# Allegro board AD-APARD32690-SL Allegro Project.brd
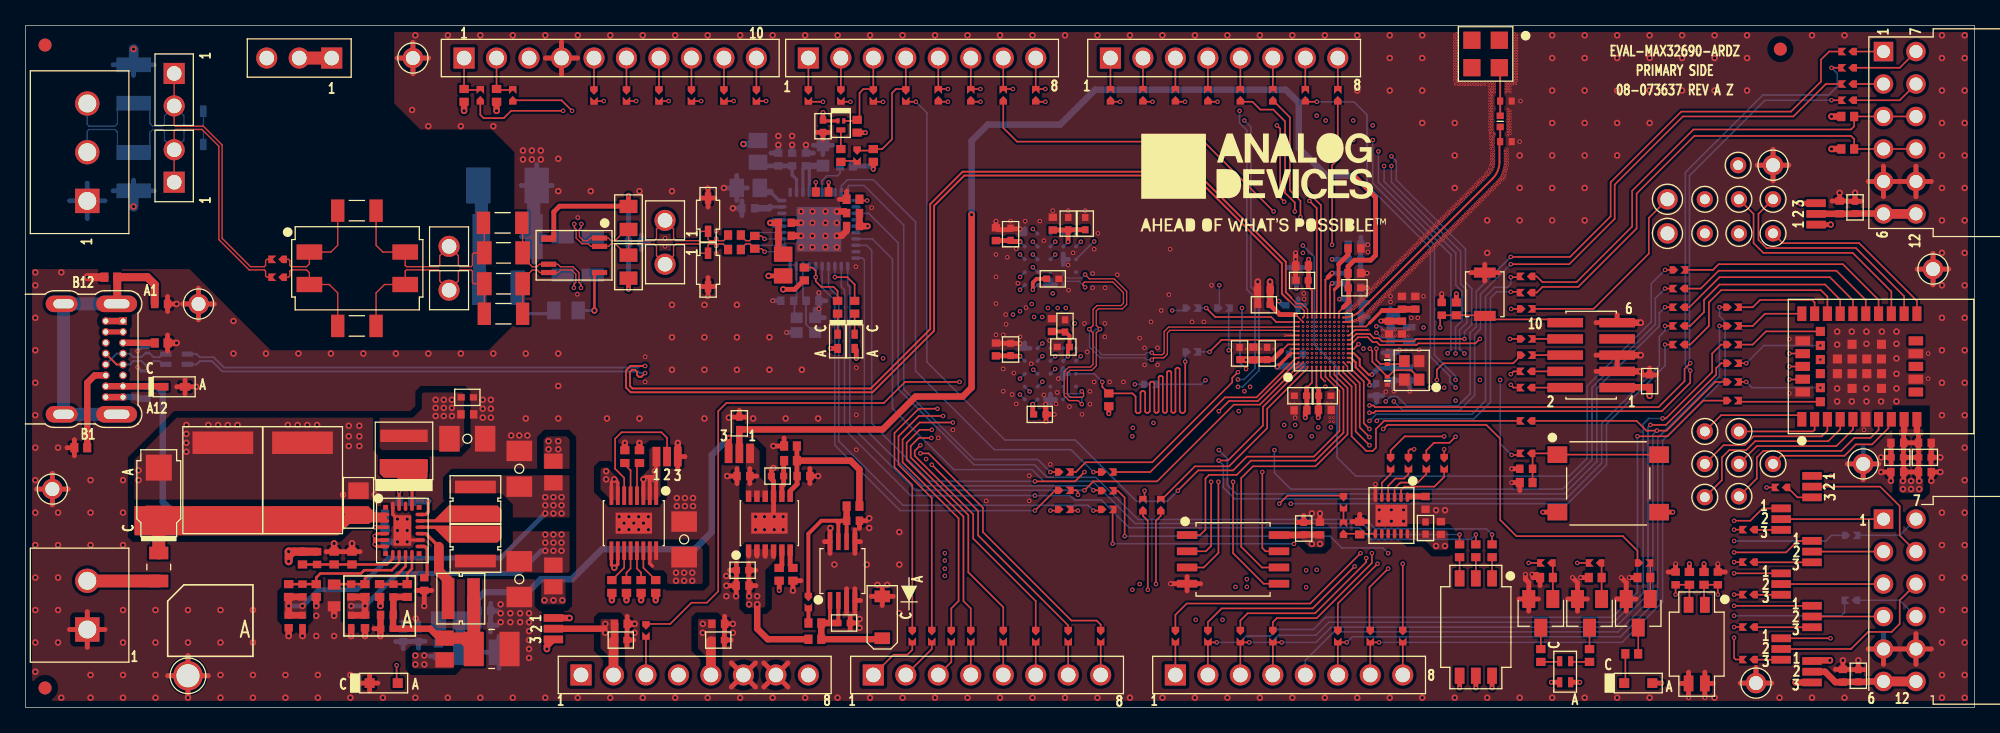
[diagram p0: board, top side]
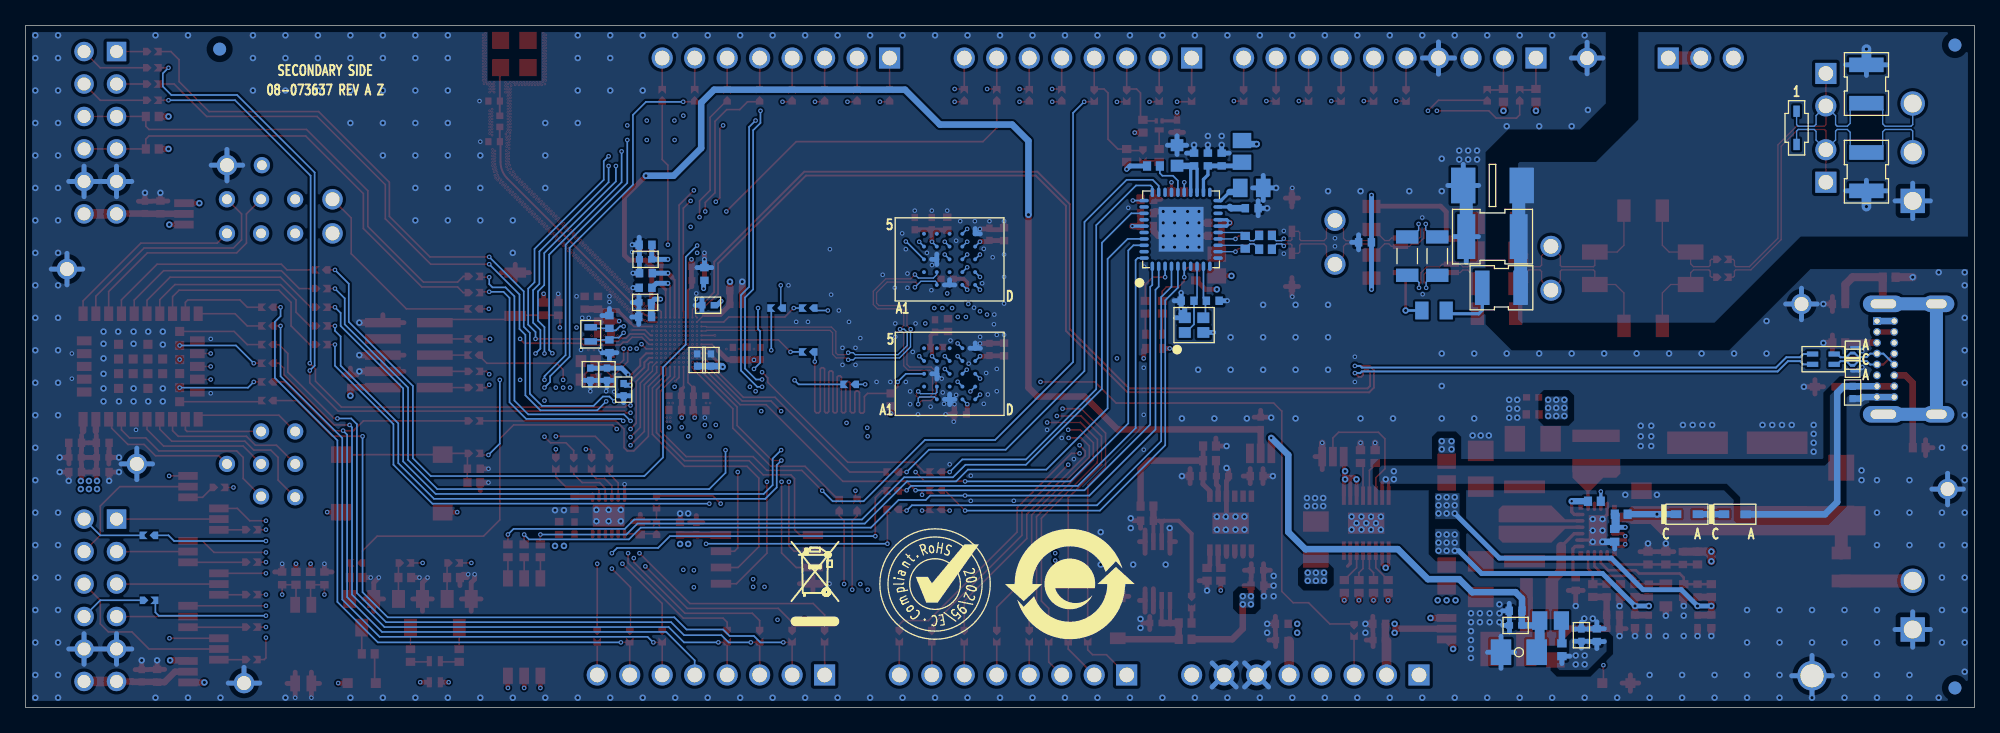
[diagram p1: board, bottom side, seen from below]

Outline 152.4 x 53.34 mm; copper layers: TOP, L2_GND, L3_SIG, L4_GND, L5_PWR, L6_PWR, L7_GND, L8_SIG, L9_GND, BOTTOM. Coordinates in mm from the lower left corner of the outline.
Outline path: 0,53.34 152.4,53.34 152.4,0 0,0 0,53.34

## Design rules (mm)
constraint set DEFAULT: min track width 0.127
net group 90_1: nets USB_DN_CM USB_DP_CM
net group 90_2: nets USB_DN USB_DP
net group 100_CLK: nets HYP_CLK_N HYP_CLK_P
net group 100C_1: nets PI+ PI-
net group 100C_2: nets UNNAMED_7_CHOKE4PV5_I912_N1 UNNAMED_7_CHOKE4PV5_I912_N2
net group 100C_3: nets UNNAMED_7_CAP_I819_N2 UNNAMED_7_CAP_I823_N2
net group 100C_4: nets UNNAMED_7_CAP_I819_N1 UNNAMED_7_CAP_I823_N1
net group 100C_5: nets TRX_N TRX_P
net group 100C_6: nets RXP TXN
net group 100C_7: nets RXN TXP

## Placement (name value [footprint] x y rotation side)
ANT1  479480001  [ASML126W126H161]  114.17 51.12 270 top
C1  4.7pF  [C0402]  22.8 11.68 90 top
C2  22uF  [CAPSML256W217H217]  21.65 17.78 270 top
C3  4.7uF  [C0805H53]  26.04 16 270 top
C4  4.7pF  [C0402]  21.65 9.14 270 top
C5  1uF  [C0402]  31.18 9.65 270 top
C6  4.7pF  [C0402]  25.46 9.14 270 top
C7  220uF  [C1210-2]  36.45 4.57 180 top
C8  47uF  [C1206H71]  34.54 21.02 180 top
C9  4.7pF  [C0402]  28.77 9.14 270 top
C10  47uF  [C1206H71]  38.61 10.03 90 top
C11  4.7uF  [C0402]  34.54 22.92 180 top
C12  47uF  [C1206H71]  38.61 18.67 270 top
C13  0.47uF  [C0402H22]  34.54 24.26 0 top
C14  47uF  [C1206H71]  51.5 13.14 270 top
C15  22uF  [CAPSML256W217H217]  15.43 17.78 270 top
C16  4.7uF  [C0402]  26.54 6.73 90 top
C17  4.7uF  [C0402]  28.26 7.24 0 top
C18  4700pF  [C0402]  103.92 35.91 0 top
C19  4.7uF  [C0402]  99.69 23.24 0 top
C20  0.47uF  [C0402H22]  99.69 24.38 180 top
C21  1uF  [C0402]  96.84 32.64 180 top
C22  1uF  [C0402]  103.89 33.97 0 bottom
C23  4.7uF  [C0402]  96.01 27.69 270 top
C24  1uF  [C0402]  103.95 30.54 0 bottom
C25  1uF  [C0402]  103.92 32.83 0 bottom
C26  1uF  [C0402]  103.92 36.2 0 bottom
C27  1uF  [C0402]  99.82 34.54 180 top
C28  1uF  [C0402]  101.6 23.27 0 top
C29  0.1uF  [C0402]  106.62 29.72 90 top
C30  0.1uF  [C0402]  107.63 31.65 270 top
C31  1uF  [C0402]  107.63 29.72 270 top
C32  0.47uF  [C0402H22]  94.93 27.69 90 top
C33  1uF  [C0402]  108.68 31.65 90 top
C34  4.7uF  [C0402]  29.53 5.65 270 bottom
C35  1uF  [C0402]  99.31 33.91 90 bottom
C36  0.47uF  [C0402H22]  30.73 5.65 90 bottom
C37  47uF  [C1206H71]  35.62 4.32 180 bottom
C38  4.7uF  [C0402]  35.88 7.56 180 bottom
C39  0.47uF  [C0402H22]  35.88 6.41 0 bottom
C40  1uF  [C0402]  101.22 14 90 top
C41  1.2pF  [C0402]  115.76 44.26 180 top
C42  0.47uF  [C0402H22]  62.36 45.47 270 top
C43  1.2pF  [C0402]  115.76 47.43 180 top
C44  12pF  [C0201]  106.49 25.55 270 top
C45  6PF  [C0402]  106.74 30.16 90 bottom
C46  1uF  [C0402]  80.33 37.85 90 top
C47  0.47uF  [C0402H22]  108.24 26.07 270 bottom
C48  4.7uF  [C0402]  103.92 33.97 180 top
C49  1uF  [C0402]  75.88 37.02 90 top
C50  0.47uF  [C0402H22]  99.03 31.46 0 bottom
C51  0.47uF  [C0402H22]  103.92 32.83 0 top
C52  12pF  [C0201]  106.49 27.18 90 top
C53  6PF  [C0402]  106.74 28.25 270 bottom
C54  1uF  [C0402]  75.88 28 90 top
C55  0.1uF  [C0402]  110.74 31.18 270 top
C56  0.47uF  [C0402H22]  101.6 24.38 0 top
C57  0.1uF  [C0402]  117.35 18.67 0 top
C58  0.47uF  [C0402H22]  97.09 27.69 90 top
C59  1uF  [C0402]  80.26 29.91 90 top
C60  0.47uF  [C0402H22]  103.95 31.69 0 bottom
C61  0.47uF  [C0402H22]  106.93 26.07 270 bottom
C62  15pF  [C0402]  61.53 31.81 0 bottom
C63  15pF  [C0402]  59.56 31.81 180 bottom
C64  0.01uF  [C0402]  59.37 37.91 180 top
C65  0.01uF  [C0402]  59.94 42.86 270 bottom
C66  0.47uF  [C0402H22]  98.81 27.18 90 bottom
C67  0.47uF  [C0402H22]  96.84 31.5 180 top
C68  0.68uF  [C0603]  62.36 43.18 90 bottom
C69  0.01uF  [C0402]  64.71 37.66 180 top
C70  0.47uF  [C0402H22]  99.82 33.4 180 top
C71  0.47uF  [C0402H22]  99.89 27.18 90 bottom
C72  0.1uF  [C0402]  56.52 39.05 0 bottom
C73  1UF  [C0805H55]  56.52 40.64 180 bottom
C74  0.47uF  [C0402H22]  105.63 24.86 270 bottom
C75  0.47uF  [C0402H22]  103.92 35.05 0 bottom
C76  0.47uF  [C0402H22]  99.95 14 90 top
C77  0.1uF  [C0402]  132.33 10.1 270 top
C78  0.1uF  [C0402]  129.03 10.1 270 top
C79  0.47uF  [C0402H22]  82.87 37.85 90 top
C80  0.47uF  [C0402H22]  81.53 37.85 90 top
C81  0.47uF  [C0402H22]  80.33 33.53 0 top
C82  0.47uF  [C0402H22]  77.03 37.02 90 top
C83  0.47uF  [C0402H22]  79.31 22.92 0 top
C84  0.47uF  [C0402H22]  77.03 28 90 top
C85  0.47uF  [C0402H22]  81.15 28.19 180 top
C86  0.01uF  [C0402]  146.37 20.7 180 top
C87  0.47uF  [C0402H22]  81.28 29.84 90 top
C88  0.1uF  [C0402]  58.86 42.86 90 bottom
C89  0.01uF  [C0402]  148.53 20.7 0 top
C90  0.1uF  [C0402]  59.37 36.89 0 top
C91  1uF  [C0402]  109.47 16 270 top
C92  0.1uF  [C0402]  64.71 38.67 0 top
C93  0.1uF  [C0402]  61.02 42.86 270 bottom
C94  0.1uF  [C0402]  47.66 36.39 0 bottom
C95  4.7uF  [C0402]  20.57 6.73 90 top
C96  0.47uF  [C0402H22]  21.65 6.73 270 top
C97  150pF  [C0805H30]  47.15 38.29 270 top
C98  0.47uF  [C0402H22]  25.46 6.73 270 top
C99  150pF  [C0805H30]  47.15 34.48 270 top
C100  0.47uF  [C0402H22]  28.26 6.16 180 top
C101  0.22uF  [C1206]  37.37 35.56 180 top
C102  0.22uF  [C1206]  37.37 33.15 180 top
C103  1000pF  [C1812H71]  37.69 36.83 180 bottom
C104  100PF  [C1210H75]  8.45 41.91 270 bottom
C105  100PF  [C1210H75]  36.99 32.83 180 bottom
C106  100PF  [C1210H75]  8.45 48.77 90 bottom
C107  4.7uF  [C0402]  46.55 6.54 180 top
C108  0.47uF  [C0402H22]  46.55 5.27 0 top
C109  4.7uF  [C0402]  141.86 39.12 270 top
C110  4.7uF  [C0402]  54.17 6.54 180 top
C111  0.47uF  [C0402H22]  143.07 39.12 90 top
C112  0.47uF  [C0402H22]  54.17 5.27 0 top
C113  4.7uF  [C0402]  142.11 2.48 270 top
C114  0.47uF  [C0402H22]  143.32 2.48 90 top
C115  4.7uF  [C0402]  146.37 18.41 0 top
C116  0.47uF  [C0402H22]  146.37 19.56 180 top
C117  4.7uF  [C0402]  148.53 18.41 180 top
C118  0.47uF  [C0402H22]  148.53 19.56 0 top
C119  0.47uF  [C0402H22]  127 25.53 90 top
C120  0.47uF  [C0402H22]  9.52 24.64 270 bottom
C121  4.7uF  [C0402]  110.68 14.03 270 top
C122  0.47uF  [C0402H22]  109.47 14.03 90 top
C123  0.1uF  [C0402]  10.6 31.56 180 top
C124  4.7uF  [C0402]  60.83 18.1 180 top
C125  2.2uF  [C0402H22]  58.8 18.1 0 top
C126  4.7uF  [C0402]  56.07 9.53 0 top
C127  0.47uF  [C0402H22]  56.07 10.73 180 top
C128  4.7uF  [C0402]  56.13 18.1 0 top
C129  0.47uF  [C0402H22]  55.82 22.23 90 top
C130  0.47uF  [C0402H22]  64.01 6.6 0 top
C131  4.7uF  [C0402]  64.71 14.61 180 top
D1  MBRA160T3G  [SMA]  10.41 16.76 90 top
D2  SP4020-01FTG  [SOD323_B]  53.37 38.54 90 top
D3  1N4148X-TP  [SOD523_B]  18.73 15.11 180 bottom
D4  1N4148X-TP  [SOD523_B]  22.48 15.11 180 bottom
D5  APTB1612ESGC-F01  [LEDSML63W49H33]  120.4 2.79 90 top
D6  SESD0201X1UN-0020-09  [D0201]  9.52 26.54 270 bottom
D7  SESD0201X1UN-0020-09  [D0201]  9.52 27.94 90 bottom
D8  D55V0M1B2WSQ-7  [SOD323_B]  13.91 45.34 270 bottom
D9  SP4020-01FTG  [SOD323_B]  53.37 34.23 270 top
D10  1N4148X-TP  [SOD523_B]  11.62 25.08 0 top
D11  BZT52C2V0-7-F  [SOD123-2]  66.99 7.05 90 top
DS1  LTST-S220TBKT  [LED0804]  28 1.91 0 top
DS2  LTST-S220TBKT  [LED0804]  126.11 1.91 0 top
DS3  APHHS1005CGCK  [LED0402_A]  64.83 28.64 270 top
DS4  APHHS1005LSYCK/J3-PF  [LED0402_A]  63.5 28.64 270 top
E1  100OHM  [L0805]  41.27 18.41 90 top
E2  100OHM  [L0805]  41.27 10.29 270 top
E3  100OHM  [L0805]  32.77 4.57 270 top
E4  100OHM  [L0805]  33.15 6.79 0 bottom
E5  100OHM  [L0805]  57.28 43.5 270 bottom
E6  100OHM  [L0805]  59.25 34.61 90 top
F3  0.5A  [F0805]  10.41 10.99 90 top
JP1  3PIN_SOLDER_JUMPER  [JPRSLD03]  50.16 19.62 0 top
JP2  3PIN_SOLDER_JUMPER  [JPRSLD03]  41.27 6.16 270 top
JP3  3PIN_SOLDER_JUMPER  [JPRSLD03]  140.02 38.61 90 top
JP4  3PIN_SOLDER_JUMPER  [JPRSLD03]  139.7 2.79 270 top
JP5  3PIN_SOLDER_JUMPER  [JPRSLD03]  139.7 17.27 270 top
JP6  3PIN_SOLDER_JUMPER  [JPRSLD03]  137.29 4.57 270 top
JP7  3PIN_SOLDER_JUMPER  [JPRSLD03]  139.7 12.19 270 top
JP8  3PIN_SOLDER_JUMPER  [JPRSLD03]  137.29 9.65 270 top
JP9  3PIN_SOLDER_JUMPER  [JPRSLD03]  137.29 14.73 270 top
JP10  3PIN_SOLDER_JUMPER  [JPRSLD03]  139.7 7.11 270 top
JP11  3PIN_SOLDER_JUMPER  [JPRSLD03]  55.82 19.88 180 top
L1  600nH  [LSMSQ118H47]  34.04 8.51 0 top
L2  1.2UH  [LSMSQ157H122]  29.59 20.07 90 top
L3  1.5uH  [LSMSQ118H47]  35.18 16.26 90 top
L4  1uH  [LSMSQ118H47]  35.18 12.45 270 top
L5  4.3nH  [L0402]  115.32 45.85 90 top
L6  470UH  [LSML236W362H209]  25.94 34.35 270 top
L7  90OHMS AT 100MEGHZ  [L0805-4PH39]  11.81 27.24 180 bottom
M1  NINA-W102  [MNINA_W102]  145.1 26.67 0 top
NOREF  -  []  0 0 0 top
NOREF#2  -  []  152.4 0 0 top
NOREF#3  -  []  341.38 170.56 0 top
NOREF#4  -  []  225.37 211.79 0 top
NOREF#5  -  []  0 0 0 top
NOREF#6  -  []  -258.95 193.29 0 top
NOREF#7  -  []  244.09 60.96 0 top
NOREF#8  -  []  96.81 41.05 0 top
NOREF#9  -  [unnamed#2]  137.22 51.5 0 top
NOREF#10  -  [unnamed#2]  1.52 1.52 0 top
NOREF#11  -  []  69.6 126.24 0 top
NOREF#12  -  []  152.4 0 90 top
NOREF#13  -  []  152.4 53.34 180 top
NOREF#14  -  []  344.17 60.96 0 top
NOREF#15  -  [unnamed#2]  1.52 51.82 0 top
NOREF#16  -  []  -66.58 -125.62 0 top
NOREF#17  -  []  4.83 6.1 0 top
NOREF#18  -  []  43.43 2.54 0 top
NOREF#19  -  []  0 0 0 top
NOREF#20  -  []  0 53.34 270 top
NOREF#21  -  []  0 53.34 0 top
NOREF#22  -  []  -66.6 -125.65 0 top
NOREF#23  -  []  -66.68 -125.73 0 top
NOREF#24  -  []  152.4 0 90 top
NOREF#25  -  []  82.37 285.07 0 top
NOREF#26  -  []  0 53.34 0 top
NOREF#27  -  []  4.83 6.1 0 top
NOREF#28  -  []  252.22 67.07 0 top
NOREF#29  -  [unnamed#2]  137.22 51.5 180 bottom
NOREF#30  -  []  70.74 9.65 180 bottom
NOREF#31  -  [unnamed#2]  1.52 1.52 180 bottom
NOREF#32  -  [unnamed#2]  1.52 51.82 180 bottom
NOREF#33  -  []  90.87 6.41 180 bottom
NOREF#34  -  []  81.28 9.65 180 bottom
P1  TBP02R2-381-03BE  [CNCUITBP02R2-381-03]  4.83 39.62 90 top
P2  SSQ-108-03-G-S  [CNSAMTECSSQ-108-XX-X-S]  43.43 2.54 0 top
P3  SSQ-108-03-G-S  [CNSAMTECSSQ-108-XX-X-S]  66.29 2.54 0 top
P4  SSQ-108-03-G-S  [CNSAMTECSSQ-108-XX-X-S]  89.92 2.54 0 top
P5  SSQ-110-03-G-S  [CNSAMTECSSQ-110-XX-X-S]  34.29 50.8 0 top
P6  SSQ-108-03-G-S  [CNSAMTECSSQ-108-XX-X-S]  61.21 50.8 0 top
P7  SSQ-108-03-G-S  [CNSAMTECSSQ-108-XX-X-S]  84.84 50.8 0 top
P8  PPPC062LJBN-RC  [CNHDRRA2X6H205]  145.29 14.73 270 top
P9  FTSH-105-01-L-DV-K  [CNHDR2X5H245]  122.43 27.56 90 top
P10  2137160001  [CNMOLEX2137160001]  7.62 30.23 270 top
P11  TSW-103-07-G-S  [CNTHMHDR1X3L300W98H343]  23.94 50.8 180 top
P12  TSW-101-07-G-S  [CNTHMHDR1X1L100W100H343]  50.01 38.1 180 top
P13  PPPC062LJBN-RC  [CNHDRRA2X6H205]  145.29 51.31 270 top
P14  TBP02R2-381-02  [CNCUITTBP02R2-381-02]  4.83 6.1 90 top
P15  TSW-101-07-G-S  [CNTHMHDR1X1L100W100H343]  50.01 34.67 180 top
P16  TSW-102-07-G-S  [CNTHMHDR1X2L200W98H343]  11.62 49.59 270 top
P17  TSW-102-07-G-S  [CNTHMHDR1X2L200W98H343]  11.62 41.08 90 top
P18  NCSOLDER_BRIDGE  [NCSB]  65.02 43.18 270 top
P19  NCSOLDER_BRIDGE  [NCSB]  133.48 24 0 top
P20  NCSOLDER_BRIDGE  [NCSB]  133.48 25.46 0 top
P21  NCSOLDER_BRIDGE  [NCSB]  133.48 26.92 0 top
P22  NCSOLDER_BRIDGE  [NCSB]  133.48 28.38 0 top
P23  NCSOLDER_BRIDGE  [NCSB]  103.06 13.97 90 top
P24  1405-2  [CNKEY1405-2]  2.1 17.08 0 top
P25  1405-2  [CNKEY1405-2]  136.65 42.42 0 top
P26  0338-0-15-15-15-27-10-0  [CNMILLMAX0338]  12.7 2.48 0 top
P27  1405-2  [CNKEY1405-2]  149.16 34.29 0 top
P28  1405-2  [CNKEY1405-2]  13.53 31.56 0 top
P29  1405-2  [CNKEY1405-2]  143.7 19.05 0 top
P30  1405-2  [CNKEY1405-2]  135.32 1.91 0 top
P31  1405-2  [CNKEY1405-2]  30.29 50.8 0 top
P32  1999-3  [CNKEY1999-3]  131.32 21.59 0 top
P33  1999-3  [CNKEY1999-3]  133.98 21.59 0 top
P34  1999-3  [CNKEY1999-3]  131.32 19.05 0 top
P35  1999-3  [CNKEY1999-3]  131.32 16.45 0 top
P36  1999-3  [CNKEY1999-3]  133.98 19.05 0 top
P37  NCSOLDER_BRIDGE  [NCSB]  61.21 8.25 270 top
P38  1405-2  [CNKEY1405-2]  128.4 39.75 0 top
P39  1405-2  [CNKEY1405-2]  128.4 37.08 0 top
P40  1999-3  [CNKEY1999-3]  133.98 16.51 0 top
P41  1999-3  [CNKEY1999-3]  136.65 19.05 0 top
P42  1999-3  [CNKEY1999-3]  136.65 37.08 0 top
P43  1999-3  [CNKEY1999-3]  136.65 39.75 0 top
P44  1999-3  [CNKEY1999-3]  133.98 39.75 0 top
P45  NCSOLDER_BRIDGE  [NCSB]  133.48 31.31 0 top
P46  NCSOLDER_BRIDGE  [NCSB]  133.48 29.84 0 top
P47  1999-3  [CNKEY1999-3]  133.92 42.42 0 top
P48  1999-3  [CNKEY1999-3]  131.32 39.75 0 top
P49  1999-3  [CNKEY1999-3]  131.32 37.08 0 top
P52  1999-3  [CNKEY1999-3]  133.98 37.08 0 top
P53  TSW-101-07-G-S  [CNTHMHDR1X1L100W100H343]  33.12 36.07 0 top
P54  TSW-101-07-G-S  [CNTHMHDR1X1L100W100H343]  33.12 32.64 0 top
Q1  BSS138LT1G  [SOT23]  126.11 7.37 180 top
Q2  BSS138LT1G  [SOT23]  118.49 7.37 180 top
Q3  BSS138LT1G  [SOT23]  122.3 7.37 180 top
Q4  DMP32D5SFB-7B  [DFN3_1X0_6]  63.75 45.53 270 top
R1  1MEG  [R0402]  21.65 11.68 90 top
R2  191K  [R0402]  25.53 11.68 270 top
R3  5.76K  [R0402]  27.62 15.11 180 bottom
R4  1K  [R0402]  28.13 13.46 270 bottom
R5  1MEG  [R0402]  20.57 9.14 270 top
R6  316K  [R0402]  22.73 9.14 90 top
R7  1MEG  [R0402]  26.54 9.14 270 top
R8  806K  [R0603]  24.13 8.76 90 top
R9  124  [R0402]  48.01 19.62 270 top
R10  124  [R0402]  46.86 19.62 270 top
R11  374K  [R0402]  29.84 9.14 270 top
R12  1MEG  [R0402]  27.69 9.14 90 top
R13  47K  [R0402]  46.99 9.46 270 top
R14  47K  [R0402]  48.13 9.46 270 top
R15  47K  [R0402]  49.28 9.46 270 top
R16  47K  [R0402]  45.85 9.46 270 top
R17  1K  [R0402]  29.72 16.13 180 bottom
R18  NCSOLDER_BRIDGE  [NCSB]  87.95 25.27 0 bottom
R20  NCSOLDER_BRIDGE  [NCSB]  117.35 22.42 180 top
R21  NCSOLDER_BRIDGE  [NCSB]  68.83 47.88 270 top
R22  NCSOLDER_BRIDGE  [NCSB]  84.58 15.49 0 top
R24  NCSOLDER_BRIDGE  [NCSB]  84.58 18.41 0 top
R29  NCSOLDER_BRIDGE  [NCSB]  81.22 18.41 0 top
R30  NCSOLDER_BRIDGE  [NCSB]  122.75 11.3 180 top
R31  NCSOLDER_BRIDGE  [NCSB]  88.77 15.81 90 top
R32  NCSOLDER_BRIDGE  [NCSB]  117.35 33.72 180 top
R33  NCSOLDER_BRIDGE  [NCSB]  134.75 11.37 180 top
R34  NCSOLDER_BRIDGE  [NCSB]  134.75 6.29 180 top
R35  NCSOLDER_BRIDGE  [NCSB]  142.75 8.38 180 bottom
R36  NCSOLDER_BRIDGE  [NCSB]  129.29 32.77 180 top
R37  NCSOLDER_BRIDGE  [NCSB]  129.29 29.84 180 top
R38  NCSOLDER_BRIDGE  [NCSB]  93.66 31.24 0 bottom
R43  NCSOLDER_BRIDGE  [NCSB]  63.75 47.88 270 top
R44  NCSOLDER_BRIDGE  [NCSB]  44.45 47.88 270 top
R45  NCSOLDER_BRIDGE  [NCSB]  46.99 47.88 270 top
R46  NCSOLDER_BRIDGE  [NCSB]  54.61 47.88 270 top
R47  NCSOLDER_BRIDGE  [NCSB]  91.19 27.81 0 bottom
R48  NCSOLDER_BRIDGE  [NCSB]  66.29 47.88 270 top
R49  NCSOLDER_BRIDGE  [NCSB]  84.58 16.95 0 top
R53  NCSOLDER_BRIDGE  [NCSB]  118.94 11.3 180 top
R54  NCSOLDER_BRIDGE  [NCSB]  87.38 15.81 90 top
R55  NCSOLDER_BRIDGE  [NCSB]  81.22 16.99 0 top
R56  NCSOLDER_BRIDGE  [NCSB]  81.22 15.49 0 top
R57  NCSOLDER_BRIDGE  [NCSB]  117.35 32.45 180 top
R58  NCSOLDER_BRIDGE  [NCSB]  134.75 13.91 180 top
R59  NCSOLDER_BRIDGE  [NCSB]  134.75 8.83 180 top
R60  NCSOLDER_BRIDGE  [NCSB]  134.75 3.75 180 top
R61  NCSOLDER_BRIDGE  [NCSB]  137.29 17.21 180 top
R62  NCSOLDER_BRIDGE  [NCSB]  129.29 31.31 180 top
R63  NCSOLDER_BRIDGE  [NCSB]  129.29 28.38 180 top
R65  NCSOLDER_BRIDGE  [NCSB]  91.19 31.24 0 bottom
R69  NCSOLDER_BRIDGE  [NCSB]  52.07 47.88 270 top
R70  NCSOLDER_BRIDGE  [NCSB]  61.21 47.88 270 top
R71  NCSOLDER_BRIDGE  [NCSB]  117.35 19.88 180 top
R72  NCSOLDER_BRIDGE  [NCSB]  49.53 47.88 270 top
R73  NCSOLDER_BRIDGE  [NCSB]  57.15 47.88 270 top
R74  NCSOLDER_BRIDGE  [NCSB]  126.56 11.3 0 top
R75  NCSOLDER_BRIDGE  [NCSB]  108.14 19.11 270 top
R76  NCSOLDER_BRIDGE  [NCSB]  106.74 19.11 270 top
R77  NCSOLDER_BRIDGE  [NCSB]  84.84 47.88 90 top
R78  NCSOLDER_BRIDGE  [NCSB]  89.92 47.88 90 top
R79  NCSOLDER_BRIDGE  [NCSB]  117.35 28.83 0 top
R80  NCSOLDER_BRIDGE  [NCSB]  73.91 47.88 90 top
R81  NCSOLDER_BRIDGE  [NCSB]  71.37 47.88 90 top
R82  NCSOLDER_BRIDGE  [NCSB]  38.1 47.88 90 top
R83  NCSOLDER_BRIDGE  [NCSB]  48.51 6.03 270 top
R84  NCSOLDER_BRIDGE  [NCSB]  95 47.88 90 top
R85  NCSOLDER_BRIDGE  [NCSB]  100.08 47.88 90 top
R86  NCSOLDER_BRIDGE  [NCSB]  89.92 5.59 270 top
R87  NCSOLDER_BRIDGE  [NCSB]  97.54 5.59 270 top
R88  NCSOLDER_BRIDGE  [NCSB]  102.62 5.59 270 top
R89  NCSOLDER_BRIDGE  [NCSB]  69.34 5.59 270 top
R90  NCSOLDER_BRIDGE  [NCSB]  72.39 5.59 270 top
R91  NCSOLDER_BRIDGE  [NCSB]  76.45 5.59 270 top
R92  NCSOLDER_BRIDGE  [NCSB]  81.53 5.59 270 top
R93  NCSOLDER_BRIDGE  [NCSB]  103.06 16.07 270 top
R94  NCSOLDER_BRIDGE  [NCSB]  117.35 31.18 0 top
R95  NCSOLDER_BRIDGE  [NCSB]  110.93 19.11 270 top
R96  NCSOLDER_BRIDGE  [NCSB]  109.54 19.11 270 top
R97  NCSOLDER_BRIDGE  [NCSB]  107.7 5.59 270 top
R98  NCSOLDER_BRIDGE  [NCSB]  87.38 47.88 90 top
R99  NCSOLDER_BRIDGE  [NCSB]  92.46 47.88 90 top
R100  NCSOLDER_BRIDGE  [NCSB]  117.35 27.56 0 top
R101  NCSOLDER_BRIDGE  [NCSB]  76.45 47.88 90 top
R102  NCSOLDER_BRIDGE  [NCSB]  78.99 47.88 90 top
R103  NCSOLDER_BRIDGE  [NCSB]  35.56 47.88 90 top
R104  NCSOLDER_BRIDGE  [NCSB]  142.75 13.46 0 bottom
R105  NCSOLDER_BRIDGE  [NCSB]  97.54 47.88 90 top
R106  NCSOLDER_BRIDGE  [NCSB]  102.62 47.88 90 top
R107  NCSOLDER_BRIDGE  [NCSB]  95 5.59 270 top
R108  NCSOLDER_BRIDGE  [NCSB]  92.46 5.59 270 top
R109  NCSOLDER_BRIDGE  [NCSB]  105.16 5.59 270 top
R110  NCSOLDER_BRIDGE  [NCSB]  70.87 5.59 270 top
R111  NCSOLDER_BRIDGE  [NCSB]  73.91 5.59 270 top
R112  NCSOLDER_BRIDGE  [NCSB]  78.99 5.59 270 top
R113  NCSOLDER_BRIDGE  [NCSB]  84.07 5.59 270 top
R114  NCSOLDER_BRIDGE  [NCSB]  129.29 34.23 0 top
R115  10K  [R0402]  126.56 10.16 180 top
R116  499  [R0402]  125.6 4.19 180 top
R117  10K  [R0402]  118.94 10.16 180 top
R118  499  [R0402]  118.49 4.06 270 top
R119  10K  [R0402]  117.35 17.59 180 top
R120  10K  [R0402]  111.89 31.18 270 top
R121  10K  [R0402]  122.75 10.16 180 top
R122  499  [R0402]  122.3 4.06 270 top
R123  TBD0402  [R0402]  24.13 11.68 90 top
R124  1  [R0402]  32.26 4.51 90 bottom
R125  1.5K  [R0402]  64.2 42.35 0 bottom
R126  2.7K  [R0402]  66.29 43.18 270 top
R127  10  [R0402]  63.75 43.18 270 top
R128  10K  [R0402]  60.9 33.91 90 top
R129  10K  [R0402]  57.02 36.39 270 top
R130  4.7K  [R0402]  63.5 31.31 90 top
R131  49.9  [R0402]  55.44 36.93 180 bottom
R132  100K  [R0402]  65.02 45.47 90 top
R133  10K  [R0402]  131.25 10.1 270 top
R134  49.9  [R0402]  55.44 35.81 180 top
R135  10K  [R0402]  57.02 36.39 90 bottom
R136  10K  [R0402]  130.11 10.1 270 top
R137  10K  [R0402]  64.71 39.75 0 top
R138  4.7K  [R0402]  114.68 12.26 270 top
R139  4.7K  [R0402]  64.83 31.31 90 top
R140  4.99K  [R0402]  55.44 36.96 180 top
R141  10K  [R0402]  142.49 43.69 0 top
R142  10K  [R0402]  142.49 46.23 0 top
R143  10K  [R0402]  36.83 47.88 270 top
R144  10K  [R0402]  34.29 47.88 270 top
R145  1K  [R0402]  6.67 33.66 180 top
R146  4.99K  [R0402]  55.44 35.85 180 bottom
R147  4.7MEG  [R2010]  37.69 40.83 180 bottom
R148  0  [R1206]  44.35 35.31 270 bottom
R149  1MEG  [R1206]  37.31 37.91 180 top
R150  1MEG  [R1206]  37.37 30.8 180 top
R151  0  [R1206]  42.01 35.31 270 bottom
R152  100  [R0805]  42.26 31.05 180 bottom
R153  10K  [R1206]  25.91 38.86 180 top
R154  10K  [R1206]  25.91 29.84 180 top
R155  NCSOLDER_BRIDGE  [NCSB]  19.72 35.05 180 top
R156  NCSOLDER_BRIDGE  [NCSB]  19.72 33.66 180 top
R157  5.1K  [R0402]  10.6 28.51 180 top
R158  5.1K  [R0402]  4.32 20.32 0 top
R159  NCSOLDER_BRIDGE  [NCSB]  117.35 26.29 180 top
R160  NCSOLDER_BRIDGE  [NCSB]  142.49 51.31 180 top
R161  NCSOLDER_BRIDGE  [NCSB]  142.49 50.04 180 top
R162  NCSOLDER_BRIDGE  [NCSB]  117.35 25.02 180 top
R163  NCSOLDER_BRIDGE  [NCSB]  142.49 48.77 180 top
R164  NCSOLDER_BRIDGE  [NCSB]  142.49 47.5 180 top
R165  10K  [R0402]  104.33 14.03 90 top
R166  4.7K  [R0402]  112.14 12.26 270 top
R167  4.7K  [R0402]  113.41 12.26 270 top
R168  1.5K  [R0402]  62.29 40.32 0 top
R169  4.99K  [R0402]  59.82 19.3 180 top
R170  200K  [R0402]  58.93 10.41 90 top
R171  499  [R0402]  60.01 10.41 90 top
R172  47K  [R0402]  61.72 6.6 180 top
R173  499  [R0402]  61.72 5.33 180 top
R174  1K  [R0402]  64.71 15.75 0 top
R175  200K  [R0402]  59.82 20.45 0 top
R176  10K  [R0402]  84.71 24.07 270 top
S1  B3U-1000P  [SWSML118W98H69]  114.11 32.32 90 top
S2  PTS645SH50SMTR92LFS  [SWSMSQ236H197]  123.76 17.53 270 top
S3  KAN1102RT  [SWSML148W177H69]  130.68 4.95 180 top
S4  416131160803  [SWSML196W228H98]  113.41 6.29 180 top
T1  74930000  [TSML185W127H114_A]  42.89 35.37 180 top
U1  MAX32690GWE+  [WLCSP140_4_492X4_532H0_69]  101.47 28.57 90 top
U2  ADIN1110CCPZ  [QFN40_6X6_PAD3_5X3_5]  62.04 37.4 180 bottom
U3  LT8692SIV#PBF  [QFN20_4X3_PAD2_40X1_40_05-08-1524]  29.46 13.84 270 top
U4  LTC4415EMSE#PBF  [MSOP16_PAD2_845X1_651]  47.56 14.41 180 top
U5  MX25U6432FM2I02  [SOP8_A]  94.42 11.58 270 top
U6  S80KS5122GABHM020  [BGA24_8X6]  80.14 35.05 180 bottom
U7  S80KS5122GABHM020  [BGA24_8X6]  80.14 26.1 180 bottom
U8  MAXQ1065GTC+  [DFN12_3X3_PAD2_5X1_7]  106.81 15.01 180 top
U9  LT3040EMSE#PBF  [MSOP12_PAD2_845X1_651]  58.17 14.41 0 top
U10  LTC6655BHMS8-1.25#PBF  [MSOP8]  63.88 10.67 0 top
Y1  25MEGHZ  [YSML79W63H20]  61.02 29.91 180 bottom
Y2  32MEGHZ  [YSML79W63H20]  108.39 26.37 90 top
Y3  32.768KHZ  [YSML65W41H20]  108.2 29.19 270 bottom

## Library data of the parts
ANT1 = ANT4P_V3: User Part Number: UPN; Tolerance: N/A; alternate symbols: (); part number: ANT4P_V3_SM-479480001,E061377,ASML126W126H161; tolerance: N/A
C1 C4 C6 C9 = CAP: User Part Number: UPN; Tolerance: 0.05pF; alternate symbols: (C0402L); part number: CAP_SM-4.7PF,50V,0.05PF,E021938,C0402; tolerance: 0.05pF
C2 C15 = CAP: Tolerance: 20; User Part Number: UPN; alternate symbols: (); part number: CAP_SM-22UF,50V,20,E017662,CAPSML256W217H217; tolerance: 20
C3 = CAP: Tolerance: 10; User Part Number: UPN; alternate symbols: (); part number: CAP_SM-4.7UF,50V,10,E028468,C0805H53; tolerance: 10
C5 C21 C22 C24-C28 C31 C33 C35 C40 C46 C49 C54 C59 C91 = CAP: User Part Number: UPN; Tolerance: 10; alternate symbols: (C0402L); part number: CAP_SM-1UF,16V,10,E019219,C0402; tolerance: 10
C7 = CAP: Tolerance: 20; User Part Number: UPN; alternate symbols: (); part number: CAP_SM-220UF,6.3V,20,E031200,C1210-2; tolerance: 20
C8 C10 C12 C14 C37 = CAP: Tolerance: 20; User Part Number: UPN; alternate symbols: (); part number: CAP_SM-47UF,16V,20,E033215,C1206H71; tolerance: 20
C11 C16 C17 C19 C23 C34 C38 C48 C95 C107 C109 C110 C113 C115 C117 C121 C124 C126 C128 C131 = CAP: User Part Number: UPN; Tolerance: 10; alternate symbols: (C0402L); part number: CAP_SM-4.7UF,6.3V,10,E020089,C0402; tolerance: 10
C13 C20 C32 C36 C39 C42 C47 C50 C51 C56 C58 C60 C61 C66 C67 C70 C71 C74-C76 C79-C85 C87 C96 C98 C100 C108 C111 C112 C114 C116 C118-C120 C122 C127 C129 C130 = CAP: Tolerance: 10; User Part Number: UPN; alternate symbols: C0402L_ALT; part number: CAP_SM-0.47UF,6.3V,10,E030257,C0402H22; tolerance: 10
C18 = CAP: User Part Number: UPN; Tolerance: 10; alternate symbols: (C0402L); part number: CAP_SM-4700PF,50V,10,E000289,C0402; tolerance: 10
C29 C30 C55 C57 C72 C77 C78 C88 C90 C92-C94 C123 = CAP: User Part Number: UPN; Tolerance: 10; alternate symbols: (C0402L_ALT,C0402L); part number: CAP_SM-0.1UF,50V,10,E026461,C0402; tolerance: 10
C41 C43 = CAP: User Part Number: UPN; Tolerance: 0.25pF; alternate symbols: (C0402L); part number: CAP_SM-1.2PF,50V,0.25PF,E032690,C0402; tolerance: 0.25pF
C44 C52 = CAP: Tolerance: 5; User Part Number: UPN; alternate symbols: (C0201L); part number: CAP_SM-12PF,50V,5,E020029,C0201; tolerance: 5
C45 C53 = CAP: User Part Number: UPN; Tolerance: 0.1pF; alternate symbols: (C0402L); part number: CAP_SM-6PF,50V,0.1PF,E045002,C0402; tolerance: 0.1pF
C62 C63 = CAP: User Part Number: UPN; Tolerance: 1; alternate symbols: (C0402L); part number: CAP_SM-15PF,50V,1,E020722,C0402; tolerance: 1
C64 C65 C69 = CAP: User Part Number: UPN; Tolerance: 10; alternate symbols: (C0402L); part number: CAP_SM-0.01UF,100V,10,E032295,C0402; tolerance: 10
C68 = CAP: User Part Number: UPN; Tolerance: 10; alternate symbols: (C0603L); part number: CAP_SM-0.68UF,10V,10,E035107,C0603; tolerance: 10
C73 = CAP: User Part Number: UPN; Tolerance: 10; alternate symbols: (); part number: CAP_SM-1UF,100V,10,E048499,C0805H55; tolerance: 10
C86 C89 = CAP: User Part Number: UPN; Tolerance: 10; alternate symbols: (C0402L); part number: CAP_SM-0.01UF,25V,10,E013688,C0402; tolerance: 10
C97 C99 = CAP: Tolerance: 1; User Part Number: UPN; alternate symbols: (); part number: CAP_SM-150PF,50V,1,E033595,C0805H30; tolerance: 1
C101 C102 = CAP: User Part Number: UPN; Tolerance: 10; alternate symbols: (C1206L); part number: CAP_SM-0.22UF,50V,10,E013767,C1206; tolerance: 10
C103 = CAP: Tolerance: 10; User Part Number: UPN; alternate symbols: (); part number: CAP_SM-1000PF,3000V,10,E023441,C1812H71; tolerance: 10
C104-C106 = CAP: User Part Number: UPN; Tolerance: 10; alternate symbols: (); part number: CAP_SM-100PF,2000V,10,E048915,C1210H75; tolerance: 10
C125 = CAP: Tolerance: 20; User Part Number: UPN; alternate symbols: (); part number: CAP_SM-2.2UF,6.3V,20,E015930,C0402H22; tolerance: 20
D1 = DIOSCHOTTKY: User Part Number: UPN; Tolerance: N/A; alternate symbols: (); part number: DIOSCHOTTKY_SM-MBRA160T3G,60V,N/A,E005910,SMA; tolerance: N/A
D2 D9 = DIOZNR_V4: Tolerance: N/A; User Part Number: UPN; alternate symbols: (); part number: DIOZNR_V4_SM-SP4020-01FTG,3.3V,N/A,E028177,SOD323_B; tolerance: N/A
D3 D4 D10 = DIO: Tolerance: N/A; User Part Number: UPN; alternate symbols: (); part number: DIO_SM-1N4148X-TP,75V,N/A,E039538,SOD523_B; tolerance: N/A
D5 = DIOLED_4P_V5: Tolerance: www.kingbright.com; User Part Number: UPN; alternate symbols: (); part number: DIOLED_4P_V5_SM-APTB1612ESGC-F01,2V/2.2V,N/A,E028120,LEDSML63W49H33; tolerance: www.kingbright.com
D6 D7 = DIO: Tolerance: N/A; User Part Number: UPN; alternate symbols: (); part number: DIO_SM-SESD0201X1UN-0020-09,9V,N/A,E022225,D0201; tolerance: N/A
D8 = DIOZNR_V2: Tolerance: N/A; User Part Number: UPN; alternate symbols: (); part number: DIOZNR_V2_SM-D55V0M1B2WSQ-7,100V,N/A,E048935,SOD323_B; tolerance: N/A
D11 = DIOZNR: User Part Number: UPN; Tolerance: 5; alternate symbols: (); part number: DIOZNR_SM-BZT52C2V0-7-F,2V,5,E026228,SOD123-2; tolerance: 5
DS1 DS2 = DIOLED: User Part Number: UPN; Tolerance: N/A; alternate symbols: LED0804_RA; part number: DIOLED_SM-LTST-S220TBKT,3.3V,N/A,E026167,LED0804; tolerance: N/A
DS3 = DIOLED: User Part Number: UPN; Tolerance: N/A; alternate symbols: (); part number: DIOLED_SM-APHHS1005CGCK,2.1V,N/A,E029804,LED0402_A; tolerance: N/A
DS4 = DIOLED: User Part Number: UPN; Tolerance: N/A; alternate symbols: (); part number: DIOLED_SM-APHHS1005LSYCK/J3-PF,1.85V,N/A,E032958,LED0402_A; tolerance: N/A
E1-E6 = FERRITE: User Part Number: UPN; Tolerance: 25; alternate symbols: (L0805L); part number: FERRITE_SM-100OHM,25,E012241,L0805; tolerance: 25
F3 = FSFUSE: User Part Number: UPN; Tolerance: N/A; alternate symbols: (); part number: FSFUSE_SM-0.5A,6V,E016128,F0805; tolerance: N/A
JP1-JP11 = NC3P_JMPR: Tolerance: N/A; User Part Number: UPN; alternate symbols: (); part number: NC3P_JMPR_SM-3PIN_SOLDER_JUMPER,E005606,JPRSLD03; tolerance: N/A
L1 = IND: Tolerance: 20; User Part Number: UPN; alternate symbols: (); part number: IND_SM-600NH,20,E019410,LSMSQ118H47; tolerance: 20
L2 = IND: User Part Number: UPN; Tolerance: 20; alternate symbols: (); part number: IND_SM-1.2UH,20,E030942,LSMSQ157H122; tolerance: 20
L3 = IND: Tolerance: 20; User Part Number: UPN; alternate symbols: (); part number: IND_SM-1.5UH,20,E022829,LSMSQ118H47; tolerance: 20
L4 = IND: Tolerance: 20; User Part Number: UPN; alternate symbols: (); part number: IND_SM-1UH,20,E015810,LSMSQ118H47; tolerance: 20
L5 = IND: User Part Number: UPN; Tolerance: 0.3nH; alternate symbols: (L0402L); part number: IND_SM-4.3NH,0.3NH,E017364,L0402; tolerance: 0.3nH
L6 = CHOKE4P_V5: User Part Number: UPN; Tolerance: 50; alternate symbols: (); part number: CHOKE4P_V5_SM-470UH,50,E032119,LSML236W362H209; tolerance: 50
L7 = CHOKE4P: User Part Number: UPN; Tolerance: 25; alternate symbols: (); part number: CHOKE4P_SM-90OHMS AT 100MEGHZ,25,E027226,L0805-4PH39; tolerance: 25
M1 = MODNINA_W10X: User Part Number: UPN; Tolerance: N/A; alternate symbols: (); part number: MODNINA_W10X_SM-NINA-W102,E038406,MNINA_W102; tolerance: N/A
P1 = CN3P: User Part Number: UPN; Tolerance: N/A; alternate symbols: (); part number: CN3P_TH-TBP02R2-381-03BE,E061218,CNCUITBP02R2-381-03; tolerance: N/A
P2-P4 P6 P7 = CN8P_A: User Part Number: UPN; Tolerance: N/A; alternate symbols: (); part number: CN8P_A_TH-SSQ-108-03-G-S,E020478,CNSAMTECSSQ-108-XX-X-S; tolerance: N/A
P5 = CN10P: User Part Number: UPN; Tolerance: N/A; alternate symbols: (); part number: CN10P_TH-SSQ-110-03-G-S,E020479,CNSAMTECSSQ-110-XX-X-S; tolerance: N/A
P8 P13 = CN12P_V3: User Part Number: UPN; Tolerance: N/A; alternate symbols: (); part number: CN12P_V3_TH-PPPC062LJBN-RC,E022332,CNHDRRA2X6H205; tolerance: N/A
P9 = CN10P_ODD_EVEN: Tolerance: N/A; User Part Number: UPN; alternate symbols: (); part number: CN10P_ODD_EVEN_SM-FTSH-105-01-L-DV-K,E023407,CNHDR2X5H245; tolerance: N/A
P10 = CN16PAB_4GND: Tolerance: N/A; User Part Number: UPN; alternate symbols: (); part number: CN16PAB_4GND_TH-2137160001,E052752,CNMOLEX2137160001; tolerance: N/A
P11 = CN3P: User Part Number: UPN; Tolerance: N/A; alternate symbols: (); part number: CN3P_TH-TSW-103-07-G-S,E042653,CNTHMHDR1X3L300W98H343; tolerance: N/A
P12 P15 P53 P54 = CN1P: User Part Number: UPN; Tolerance: N/A; alternate symbols: (); part number: CN1P_TH-TSW-101-07-G-S,E028213,CNTHMHDR1X1L100W100H343; tolerance: N/A
P14 = CN2P: Tolerance: N/A; alternate symbols: (); part number: CN2P_TH-TBP02R2-381-02BE,E061381,CNCUITTBP02R2-381-02; tolerance: N/A
P16 P17 = CN2P: User Part Number: UPN; Tolerance: N/A; alternate symbols: (); part number: CN2P_TH-TSW-102-07-G-S,E031850,CNTHMHDR1X2L200W98H343; tolerance: N/A
P18-P23 P37 P45 P46 = NC2P: User Part Number: UPN; Tolerance: N/A; alternate symbols: (); part number: NC2P_SM-NCSOLDER_BRIDGE,E043778,NCSB; tolerance: N/A
P24 P25 P27-P31 P38 P39 = CN1P: Tolerance: N/A; User Part Number: UPN; alternate symbols: (); part number: CN1P_TH-1405-2,E022242,CNKEY1405-2; tolerance: N/A
P26 = CN1P: User Part Number: UPN; Tolerance: N/A; alternate symbols: (); part number: CN1P_TH-0338-0-15-15-15-27-10-0,E057326,CNMILLMAX0338; tolerance: N/A
P32-P36 P40-P44 P47-P49 P52 = CN1P: Tolerance: N/A; User Part Number: UPN; alternate symbols: (); part number: CN1P_TH-1999-3,E020606,CNKEY1999-3; tolerance: N/A
Q1-Q3 = TRANNMOSFET_V8: User Part Number: UPN; Tolerance: N/A; part number: TRANNMOSFET_V8_SM-BSS138LT1G,E018770,SOT23; tolerance: N/A
Q4 = TRANPMOSFET_V17: User Part Number: UPN; Tolerance: N/A; alternate symbols: (); part number: TRANPMOSFET_V17_SM-DMP32D5SFB-7B,E031823,DFN3_1X0_6; tolerance: N/A
R1 R5 R7 R12 = RES: User Part Number: UPN; Tolerance: 1; alternate symbols: (R0402L); part number: RES_SM-1MEG,E003749,1/10W,1,R0402; tolerance: 1
R2 = RES: User Part Number: UPN; Tolerance: 1; alternate symbols: (R0402L); part number: RES_SM-191K,E035329,1/10W,1,R0402; tolerance: 1
R3 = RES: User Part Number: UPN; Tolerance: 1; alternate symbols: (R0402L); part number: RES_SM-5.76K,E025055,1/10W,1,R0402; tolerance: 1
R4 R17 R145 R174 = RES: User Part Number: UPN; Tolerance: 1; alternate symbols: (R0402L,R0402L_ALT); part number: RES_SM-1K,E003763,1/10W,1,R0402; tolerance: 1
R6 = RES: User Part Number: UPN; Tolerance: 1; alternate symbols: (R0402L); part number: RES_SM-316K,E008277,1/10W,1,R0402; tolerance: 1
R8 = RES: User Part Number: UPN; Tolerance: 1; alternate symbols: (R0603L); part number: RES_SM-806K,E033372,1/10W,1,R0603; tolerance: 1
R9 R10 = RES: User Part Number: UPN; Tolerance: 1; alternate symbols: (R0402L); part number: RES_SM-124,E043017,1/10W,1,R0402; tolerance: 1
R11 = RES: User Part Number: UPN; Tolerance: 1; alternate symbols: (R0402L); part number: RES_SM-374K,E022652,1/10W,1,R0402; tolerance: 1
R13-R16 R172 = RES: User Part Number: UPN; Tolerance: 1; alternate symbols: (R0402L,R0402L_ALT); part number: RES_SM-47K,E008189,1/10W,1,R0402; tolerance: 1
R18 R20-R22 R24 R29-R38 R43-R49 R53-R63 R65 R69-R114 R155 R156 R159-R164 = NC2P: User Part Number: UPN; Tolerance: N/A; alternate symbols: (R0402L,R0402L_ALT); part number: NC2P_SM-NCSOLDER_BRIDGE,E043778,NCSB; tolerance: N/A
R115 R117 R119-R121 R128 R129 R133 R135-R137 R141-R144 R165 R176 = RES: User Part Number: UPN; Tolerance: 1; alternate symbols: (R0402L,R0402L_ALT); part number: RES_SM-10K,E003751,1/10W,1,R0402; tolerance: 1
R116 R118 R122 R171 R173 = RES: User Part Number: UPN; Tolerance: 1; alternate symbols: (R0402L); part number: RES_SM-499,E003758,1/10W,1,R0402; tolerance: 1
R123 = RES: User Part Number: UPN; alternate symbols: (R0402L,R0402L_ALT); part number: RES_SM-TBD0402,E004049,TBD0402,TBD0402,R0402
R124 = RES: User Part Number: UPN; alternate symbols: (R0402L); part number: RES_SM-1,E020530,1/6W,1,R0402
R125 R168 = RES: User Part Number: UPN; Tolerance: 1; alternate symbols: (R0402L); part number: RES_SM-1.5K,E003782,1/10W,1,R0402; tolerance: 1
R126 = RES: User Part Number: UPN; Tolerance: 1; alternate symbols: (R0402L); part number: RES_SM-2.7K,E007440,1/10W,1,R0402; tolerance: 1
R127 = RES: User Part Number: UPN; Tolerance: 5; alternate symbols: (R0402L); part number: RES_SM-10,E042731,1/10W,5,R0402; tolerance: 5
R130 R138 R139 R166 R167 = RES: User Part Number: UPN; Tolerance: 5; alternate symbols: (R0402L); part number: RES_SM-4.7K,E042730,1/10W,5,R0402; tolerance: 5
R131 R134 = RES: User Part Number: UPN; Tolerance: 1; alternate symbols: (R0402L); part number: RES_SM-49.9,E003750,1/10W,1,R0402; tolerance: 1
R132 = RES: User Part Number: UPN; Tolerance: 5; alternate symbols: (R0402L); part number: RES_SM-100K,E003464,1/10W,5,R0402; tolerance: 5
R140 R146 R169 = RES: User Part Number: UPN; Tolerance: 1; alternate symbols: (R0402L); part number: RES_SM-4.99K,E006643,1/10W,1,R0402; tolerance: 1
R147 = RES: Tolerance: 5; User Part Number: UPN; alternate symbols: (R2010L); part number: RES_SM-4.7MEG,E031023,1/2W,5,R2010; tolerance: 5
R148 R151 = RES: User Part Number: UPN; Tolerance: 5; alternate symbols: (R1206L); part number: RES_SM-0,E010093,1/4W,5,R1206; tolerance: 5
R149 R150 = RES: User Part Number: UPN; Tolerance: 1; alternate symbols: (R1206L); part number: RES_SM-1MEG,E003331,1/4W,1,R1206; tolerance: 1
R152 = RES: User Part Number: UPN; Tolerance: 1; alternate symbols: (R0805L); part number: RES_SM-100,E003481,1/8W,1,R0805; tolerance: 1
R153 R154 = RES: User Part Number: UPN; Tolerance: 1; alternate symbols: (R1206L); part number: RES_SM-10K,E003285,1/4W,1,R1206; tolerance: 1
R157 R158 = RES: User Part Number: UPN; Tolerance: 0.1; alternate symbols: (R0402L); part number: RES_SM-5.1K,E010267,1/16W,0.1,R0402; tolerance: 0.1
R170 R175 = RES: User Part Number: UPN; Tolerance: 1; alternate symbols: (R0402L); part number: RES_SM-200K,E004033,1/10W,1,R0402; tolerance: 1
S1 = SWSPST2PIN_V2: Tolerance: N/A; User Part Number: UPN; alternate symbols: (); part number: SWSPST2PIN_V2_SM-B3U-1000P,E016303,SWSML118W98H69; tolerance: N/A
S2 = SWSPST4PIN_B: User Part Number: UPN; Tolerance: N/A; alternate symbols: (); part number: SWSPST4PIN_B_SM-PTS645SH50SMTR92LFS,E019204,SWSMSQ236H197; tolerance: N/A
S3 = SWSPST4P_V8: User Part Number: UPN; Tolerance: N/A; alternate symbols: (); part number: SWSPST4P_V8_SM-KAN1102RT,E059268,SWSML148W177H69; tolerance: N/A
S4 = SWSPST6PIN: Tolerance: N/A; User Part Number: UPN; alternate symbols: (); part number: SWSPST6PIN_SM-416131160803,E034219,SWSML196W228H98; tolerance: N/A
T1 = XFMR7P_V2: User Part Number: UPN; Tolerance: N/A; alternate symbols: (TSML185W127H114_B); part number: XFMR7P_V2_SM-74930000,E042298,TSML185W127H114_A; tolerance: N/A
U1 = ADMAX32690: User Part Number: UPN; Tolerance: N/A; alternate symbols: (WLCSP140_4_492X4_532H0_69_L); part number: ADMAX32690_SM-MAX32690GWE+,E058743,WLCSP140_4_492X4_532H0_69; tolerance: N/A
U2 = ADIN1110_V2: User Part Number: UPN; Tolerance: N/A; alternate symbols: (); part number: ADIN1110_V2_SM-ADIN1110CCPZ,E049968,QFN40_6X6_PAD3_5X3_5; tolerance: N/A
U3 = ADLT8692S: User Part Number: UPN; Tolerance: N/A; alternate symbols: (); part number: ADLT8692S_SM-LT8692SIV#PBF,E058915,QFN20_4X3_PAD2_40X1_40_05-08-1524; tolerance: N/A
U4 = LINLTC4415: Tolerance: N/A; User Part Number: UPN; alternate symbols: (); part number: LINLTC4415_SM-LTC4415EMSE#PBF,E027536,MSOP16_PAD2_845X1_651; tolerance: N/A
U5 = ICMX25U6432F_V2: User Part Number: UPN; Tolerance: N/A; alternate symbols: (); part number: ICMX25U6432F_V2_SM-MX25U6432FM2I02,E060310,SOP8_A; tolerance: N/A
U6 U7 = ICS80KS5122: Tolerance: N/A; User Part Number: UPN; alternate symbols: (BGA24_8X6_PB); part number: ICS80KS5122_SM-S80KS5122GABHM020,E060311,BGA24_8X6; tolerance: N/A
U8 = ADMAXQ1065: User Part Number: UPN; Tolerance: N/A; alternate symbols: (); part number: ADMAXQ1065_SM-MAXQ1065GTC+,E059230,DFN12_3X3_PAD2_5X1_7; tolerance: N/A
U9 = ADLT3040: Tolerance: N/A; User Part Number: UPN; alternate symbols: (); part number: ADLT3040_SM-LT3040EMSE#PBF,E040922,MSOP12_PAD2_845X1_651; tolerance: N/A
U10 = LINLTC6655: Tolerance: N/A; User Part Number: UPN; alternate symbols: (); part number: LINLTC6655_SM-LTC6655BHMS8-1.25#PBF,E032393,MSOP8; tolerance: N/A
Y1 = XTAL4PIN_V3: Tolerance: 10PPM; User Part Number: UPN; alternate symbols: (); part number: XTAL4PIN_V3_SM-25MEGHZ,E051324,YSML79W63H20; tolerance: 10PPM
Y2 = XTAL4PIN_V3: Tolerance: N/A; User Part Number: UPN; alternate symbols: (); part number: XTAL4PIN_V3_SM-32MEGHZ,E017803,YSML79W63H20; tolerance: N/A
Y3 = XTAL: User Part Number: UPN; Tolerance: 20PPM; alternate symbols: (); part number: XTAL_SM-32.768KHZ,E058949,YSML65W41H20; tolerance: 20PPM

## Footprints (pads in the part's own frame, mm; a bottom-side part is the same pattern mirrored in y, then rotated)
ASML126W126H161
  rect 1.346x1.346 smd: 1(-1.073,1.073) 2(-1.073,-1.073) 3(1.073,-1.073) 4(1.073,1.073)
BGA24_8X6
  round 0.305 smd: A2(-2,-1) A3(-2,0) A4(-2,1) A5(-2,2) B1(-1,-2) B2(-1,-1) B3(-1,0) B4(-1,1) B5(-1,2) C1(0,-2) C2(0,-1) C3(0,0) C4(0,1) C5(0,2) D1(1,-2) D2(1,-1) D3(1,0) D4(1,1) D5(1,2) E1(2,-2) E2(2,-1) E3(2,0) E4(2,1) E5(2,2)
C0201
  rect 0.305x0.406 smd: 1(-0.318,0) 2(0.318,0)
C0402
  rect 0.584x0.66 smd: 1(-0.5,0) 2(0.5,0)
C0402H22
  rect 0.559x0.508 smd: 1(-0.479,0) 2(0.479,0)
C0603
  rect 0.94x0.991 smd: 1(-0.8,0) 2(0.8,0)
C0805H30
  rect 1.041x1.397 smd: 1(-0.9,0) 2(0.9,0)
C0805H53
  rect 1.295x1.6 smd: 1(-0.953,0) 2(0.953,0)
C0805H55
  rect 1.143x1.448 smd: 1(-0.9,0) 2(0.9,0)
C1206
  rect 1.143x1.803 smd: 1(-1.5,0) 2(1.5,0)
C1206H71
  rect 1.6x2.007 smd: 1(-1.397,0) 2(1.397,0)
C1210-2
  rect 1.575x2.692 smd: 1(-1.397,0) 2(1.397,0)
C1210H75
  rect 1.143x2.692 smd: 1(-1.5,0) 2(1.5,0)
C1812H71
  rect 1.397x3.505 smd: 1(-2.05,0) 2(2.05,0)
CAPSML256W217H217
  rect 1.753x4.75 smd: 1(-2.926,0) 2(2.926,0)
CNCUITBP02R2-381-03
  rect 1.905x1.905 hole 1.397: 1(0,0)
  round 1.905 hole 1.397: 2(3.81,0) 3(7.62,0)
CNCUITTBP02R2-381-02
  rect 1.905x1.905 hole 1.397: 1(0,0)
  round 1.905 hole 1.397: 2(3.81,0)
CNHDR2X5H245
  rect 0.737x2.794 smd: 1(-2.54,-2.032) 2(-2.54,2.032) 3(-1.27,-2.032) 4(-1.27,2.032) 5(0,-2.032) 6(0,2.032) 7(1.27,-2.032) 8(1.27,2.032) 9(2.54,-2.032) 10(2.54,2.032)
CNHDRRA2X6H205
  rect 1.524x1.524 hole 1.016: 1(0,0)
  round 1.524 hole 1.016: 2(2.54,0) 3(5.08,0) 4(7.62,0) 5(10.16,0) 6(12.7,0) 7(0,2.54) 8(2.54,2.54) 9(5.08,2.54) 10(7.62,2.54) 11(10.16,2.54) 12(12.7,2.54)
CNKEY1405-2
  round 1.6 hole 1.092: 1(0,0)
CNKEY1999-3
  round 1.27 hole 0.762: 1(0,0)
CNMILLMAX0338
  round 2.311 hole 1.803: 1(0,0)
CNMOLEX2137160001
  rect 0.61x0.61 hole 0.406: A1(0,0)
  round 0.61 hole 0.406: A4(0.85,0) A5(1.7,0) A6(2.55,0) A7(3.4,0) A8(4.25,0) A9(5.1,0) A12(5.95,0) B1(5.95,-1.35) B4(5.1,-1.35) B5(4.25,-1.35) B6(3.4,-1.35) B7(2.55,-1.35) B8(1.7,-1.35) B9(0.85,-1.35) B12(0,-1.35)
  oval 1.295x3.2 hole 0.711x2.007: GND1(-1.345,-0.5) GND2(7.295,-0.5)
  oval 1.295x2.489 hole 0.711x1.6: GND3(-1.345,-4.65) GND4(7.295,-4.65)
CNSAMTECSSQ-108-XX-X-S
  rect 1.651x1.651 hole 1.143: 1(0,0)
  round 1.651 hole 1.143: 2(2.54,0) 3(5.08,0) 4(7.62,0) 5(10.16,0) 6(12.7,0) 7(15.24,0) 8(17.78,0)
CNSAMTECSSQ-110-XX-X-S
  rect 1.651x1.651 hole 1.143: 1(0,0)
  round 1.651 hole 1.143: 2(2.54,0) 3(5.08,0) 4(7.62,0) 5(10.16,0) 6(12.7,0) 7(15.24,0) 8(17.78,0) 9(20.32,0) 10(22.86,0)
CNTHMHDR1X1L100W100H343
  round 1.651 hole 1.143: 1(0,0)
CNTHMHDR1X2L200W98H343
  rect 1.651x1.651 hole 1.143: 1(0,0)
  round 1.651 hole 1.143: 2(2.54,0)
CNTHMHDR1X3L300W98H343
  rect 1.651x1.651 hole 1.143: 1(0,0)
  round 1.651 hole 1.143: 2(2.54,0) 3(5.08,0)
D0201
  rect 0.229x0.381 smd: A(0.22,0) C(-0.22,0)
DFN3_1X0_6
  rect 0.406x0.254 smd: 1(-0.353,0.227) 2(-0.353,-0.227)
  rect 0.406x0.711 smd: 3(0.353,0)
DFN12_3X3_PAD2_5X1_7
  oval 0.279x0.737 smd: 1(-1.25,-1.43) 2(-0.75,-1.43) 3(-0.25,-1.43) 4(0.25,-1.43) 5(0.75,-1.43) 6(1.25,-1.43) 7(1.25,1.43) 8(0.75,1.43) 9(0.25,1.43) 10(-0.25,1.43) 11(-0.75,1.43) 12(-1.25,1.43)
  rect 2.489x1.702 smd: PAD(0,0)
F0805
  rect 0.991x1.499 smd: 1(-1.095,0) 2(1.095,0)
JPRSLD03
  rect 0.61x1.524 smd: 1(-0.838,0) 2(0,0) 3(0.838,0)
L0402
  rect 0.508x0.559 smd: 1(-0.434,0) 2(0.434,0)
L0805
  rect 1.194x1.448 smd: 1(-0.85,0) 2(0.85,0)
L0805-4PH39
  rect 0.889x0.406 smd: 1(-0.845,-0.403) 2(0.845,-0.403) 3(0.845,0.403) 4(-0.845,0.403)
LED0402_A
  rect 0.711x0.508 smd: A(0.555,0) C(-0.555,0)
LED0804
  rect 0.787x0.762 smd: A(1.1,0) C(-1.1,0)
LEDSML63W49H33
  rect 0.787x0.406 smd: 1(-0.825,-0.43) 2(0.825,-0.43) 3(-0.825,0.43) 4(0.825,0.43)
LSML236W362H209
  rect 1.194x2.007 smd: 1(-1.27,-3.747) 2(1.27,-3.747) 3(1.27,3.747) 4(-1.27,3.747)
LSMSQ118H47
  rect 0.991x3.2 smd: 1(-0.995,0) 2(0.995,0)
LSMSQ157H122
  rect 0.965x3.708 smd: 1(-1.181,0) 2(1.181,0)
MNINA_W102
  rect 0.711x1.143 smd: 1(-6.194,-4.129) 2(-5.194,-4.129) 3(-4.194,-4.129) 4(-3.194,-4.129) 5(-2.194,-4.129) 6(-1.194,-4.129) 7(-0.194,-4.129) 8(0.806,-4.129) 9(1.806,-4.129) 10(2.806,-4.129) 16(2.806,4.129) 17(1.806,4.129) 18(0.806,4.129) 19(-0.194,4.129) 20(-1.194,4.129) 21(-2.194,4.129) 22(-3.194,4.129) 23(-4.194,4.129) 24(-5.194,4.129) 25(-6.194,4.129)
  rect 1.143x0.711 smd: 11(2.722,-1.994) 12(2.722,-0.994) 13(2.722,0.006) 14(2.722,1.006) 15(2.722,2.006) 26(-6.129,2.006) 27(-6.129,1.006) 28(-6.129,0.006) 29(-6.129,-0.994) 30(-6.129,-1.994)
  rect 0.711x0.711 smd: 31(-4.744,-2.756) 32(-4.744,-1.656) 33(-4.744,-0.555) 34(-4.744,0.544) 35(-4.744,1.644) 36(-4.744,2.744) 37(-3.415,-0.564) 38(-3.415,0.586) 39(-2.264,-1.714) 40(-2.264,-0.564) 41(-2.264,0.586) 42(-2.264,1.736) 43(-1.114,-0.564) 44(-1.114,0.586) 45(0.036,-1.714) 46(0.036,-0.564) 47(0.036,0.586) 48(0.036,1.736)
MSOP8
  rect 0.356x1.321 smd: 1(-0.975,-2.3) 2(-0.325,-2.3) 3(0.325,-2.3) 4(0.975,-2.3) 5(0.975,2.3) 6(0.325,2.3) 7(-0.325,2.3) 8(-0.975,2.3)
MSOP12_PAD2_845X1_651
  rect 0.432x0.889 smd: 1(-1.625,-2.107) 2(-0.975,-2.107) 3(-0.325,-2.107) 4(0.325,-2.107) 5(0.975,-2.107) 6(1.625,-2.107) 7(1.625,2.107) 8(0.975,2.107) 9(0.325,2.107) 10(-0.325,2.107) 11(-0.975,2.107) 12(-1.625,2.107)
  rect 2.845x1.651 smd: PAD(0,0)
MSOP16_PAD2_845X1_651
  rect 0.305x1.448 smd: 1(-1.75,-2.15) 2(-1.25,-2.15) 3(-0.75,-2.15) 4(-0.25,-2.15) 5(0.25,-2.15) 6(0.75,-2.15) 7(1.25,-2.15) 8(1.75,-2.15) 9(1.75,2.15) 10(1.25,2.15) 11(0.75,2.15) 12(0.25,2.15) 13(-0.25,2.15) 14(-0.75,2.15) 15(-1.25,2.15) 16(-1.75,2.15)
  rect 2.845x1.651 smd: PAD(0,0)
NCSB
  custom 0.148x0.148 smd: 1(-0.383,0) 2(0.423,0)
QFN20_4X3_PAD2_40X1_40_05-08-1524
  rect 0.381x0.381 smd: (-1.809,1.31) (-1.809,-1.31) (1.809,1.31) (1.809,-1.31)
  oval 0.279x0.737 smd: 1(-1.25,-1.393) 2(-0.75,-1.393) 3(-0.25,-1.393) 4(0.25,-1.393) 5(0.75,-1.393) 6(1.25,-1.393) 11(1.25,1.393) 12(0.75,1.393) 13(0.25,1.393) 14(-0.25,1.393) 15(-0.75,1.393) 16(-1.25,1.393)
  oval 0.737x0.279 smd: 7(1.893,-0.75) 8(1.893,-0.25) 9(1.893,0.25) 10(1.893,0.75) 17(-1.893,0.75) 18(-1.893,0.25) 19(-1.893,-0.25) 20(-1.893,-0.75)
  rect 2.388x1.397 smd: 21(0,0)
QFN40_6X6_PAD3_5X3_5
  oval 0.279x0.737 smd: 1(-2.25,-2.893) 2(-1.75,-2.893) 3(-1.25,-2.893) 4(-0.75,-2.893) 5(-0.25,-2.893) 6(0.25,-2.893) 7(0.75,-2.893) 8(1.25,-2.893) 9(1.75,-2.893) 10(2.25,-2.893) 21(2.25,2.893) 22(1.75,2.893) 23(1.25,2.893) 24(0.75,2.893) 25(0.25,2.893) 26(-0.25,2.893) 27(-0.75,2.893) 28(-1.25,2.893) 29(-1.75,2.893) 30(-2.25,2.893)
  oval 0.737x0.279 smd: 11(2.893,-2.25) 12(2.893,-1.75) 13(2.893,-1.25) 14(2.893,-0.75) 15(2.893,-0.25) 16(2.893,0.25) 17(2.893,0.75) 18(2.893,1.25) 19(2.893,1.75) 20(2.893,2.25) 31(-2.893,2.25) 32(-2.893,1.75) 33(-2.893,1.25) 34(-2.893,0.75) 35(-2.893,0.25) 36(-2.893,-0.25) 37(-2.893,-0.75) 38(-2.893,-1.25) 39(-2.893,-1.75) 40(-2.893,-2.25)
  rect 3.505x3.505 smd: PAD(0,0)
R0402
  rect 0.635x0.737 smd: 1(-0.5,0) 2(0.5,0)
R0603
  rect 0.787x0.991 smd: 1(-0.85,0) 2(0.85,0)
R0805
  rect 1.041x1.397 smd: 1(-0.95,0) 2(0.95,0)
R1206
  rect 1.041x1.753 smd: 1(-1.5,0) 2(1.5,0)
R2010
  rect 1.905x2.794 smd: 1(-2.286,0) 2(2.286,0)
SMA
  rect 2.032x2.032 smd: A(1.994,0) C(-1.994,0)
SOD123-2
  rect 0.914x1.219 smd: A(1.638,0) C(-1.638,0)
SOD323_B
  rect 0.889x0.508 smd: 1(-1.3,0) 2(1.3,0)
SOD523_B
  rect 0.813x0.61 smd: A(0.85,0) C(-0.85,0)
SOP8_A
  rect 0.61x1.6 smd: 1(-1.905,-3.594) 2(-0.635,-3.594) 3(0.635,-3.594) 4(1.905,-3.594) 5(1.905,3.594) 6(0.635,3.594) 7(-0.635,3.594) 8(-1.905,3.594)
SOT23
  rect 1.016x1.397 smd: 1(-0.94,-1.118) 2(0.94,-1.118) 3(0,1.118)
SWSML118W98H69
  rect 0.787x1.702 smd: 1(-1.694,0) 2(1.694,0)
SWSML148W177H69
  rect 0.762x1.245 smd: 1(-0.635,-3.075) 2(-0.635,3.075) 3(0.635,-3.075) 4(0.635,3.075)
SWSML196W228H98
  rect 0.762x1.27 smd: 1A(-1.27,-3.81) 1B(-1.27,3.81) 2A(0,-3.81) 2B(0,3.81) 3A(1.27,-3.81) 3B(1.27,3.81)
SWSMSQ236H197
  rect 1.295x1.549 smd: 1(-2.25,-3.975) 2(-2.25,3.975) 3(2.25,-3.975) 4(2.25,3.975)
TSML185W127H114_A
  rect 1.194x0.406 smd: 1(-1.99,-1.35) 2(-1.99,-0.7) 3(-1.99,1.35) 6(1.99,0.7) 7(1.99,1.35)
  round 0.127 smd: 4(-1.69,1.35)
  rect 1.194x0.508 smd: 5(1.99,-1.305)
unnamed#2
  round 1.016 smd: (0,0)
WLCSP140_4_492X4_532H0_69
  round 0.178 smd: A2(-1.575,1.925) A3(-1.225,1.925) A4(-0.875,1.925) A5(-0.525,1.925) A6(-0.175,1.925) A7(0.175,1.925) A8(0.525,1.925) A9(0.875,1.925) A10(1.225,1.925) A11(1.575,1.925) B1(-1.925,1.575) B2(-1.575,1.575) B3(-1.225,1.575) B4(-0.875,1.575) B5(-0.525,1.575) B6(-0.175,1.575) B7(0.175,1.575) B8(0.525,1.575) B9(0.875,1.575) B10(1.225,1.575) B11(1.575,1.575) B12(1.925,1.575) C1(-1.925,1.225) C2(-1.575,1.225) C3(-1.225,1.225) C4(-0.875,1.225) C5(-0.525,1.225) C6(-0.175,1.225) C7(0.175,1.225) C8(0.525,1.225) C9(0.875,1.225) C10(1.225,1.225) C11(1.575,1.225) C12(1.925,1.225) D1(-1.925,0.875) D2(-1.575,0.875) D3(-1.225,0.875) D4(-0.875,0.875) D5(-0.525,0.875) D6(-0.175,0.875) D7(0.175,0.875) D8(0.525,0.875) D9(0.875,0.875) D10(1.225,0.875) D11(1.575,0.875) D12(1.925,0.875) E1(-1.925,0.525) E2(-1.575,0.525) E3(-1.225,0.525) E4(-0.875,0.525) E5(-0.525,0.525) E6(-0.175,0.525) E7(0.175,0.525) E8(0.525,0.525) E9(0.875,0.525) E10(1.225,0.525) E11(1.575,0.525) E12(1.925,0.525) F1(-1.925,0.175) F2(-1.575,0.175) F3(-1.225,0.175) F4(-0.875,0.175) F5(-0.525,0.175) F6(-0.175,0.175) F7(0.175,0.175) F8(0.525,0.175) F9(0.875,0.175) F10(1.225,0.175) F11(1.575,0.175) F12(1.925,0.175) G1(-1.925,-0.175) G2(-1.575,-0.175) G3(-1.225,-0.175) G4(-0.875,-0.175) G5(-0.525,-0.175) G6(-0.175,-0.175) G7(0.175,-0.175) G8(0.525,-0.175) G9(0.875,-0.175) G10(1.225,-0.175) G11(1.575,-0.175) G12(1.925,-0.175) H1(-1.925,-0.525) H2(-1.575,-0.525) H3(-1.225,-0.525) H4(-0.875,-0.525) H5(-0.525,-0.525) H6(-0.175,-0.525) H7(0.175,-0.525) H8(0.525,-0.525) H9(0.875,-0.525) H10(1.225,-0.525) H11(1.575,-0.525) H12(1.925,-0.525) J1(-1.925,-0.875) J2(-1.575,-0.875) J3(-1.225,-0.875) J4(-0.875,-0.875) J5(-0.525,-0.875) J6(-0.175,-0.875) J7(0.175,-0.875) J8(0.525,-0.875) J9(0.875,-0.875) J10(1.225,-0.875) J11(1.575,-0.875) J12(1.925,-0.875) K1(-1.925,-1.225) K2(-1.575,-1.225) K3(-1.225,-1.225) K4(-0.875,-1.225) K5(-0.525,-1.225) K6(-0.175,-1.225) K7(0.175,-1.225) K8(0.525,-1.225) K9(0.875,-1.225) K10(1.225,-1.225) K11(1.575,-1.225) K12(1.925,-1.225) L1(-1.925,-1.575) L2(-1.575,-1.575) L3(-1.225,-1.575) L4(-0.875,-1.575) L5(-0.525,-1.575) L6(-0.175,-1.575) L7(0.175,-1.575) L8(0.525,-1.575) L9(0.875,-1.575) L10(1.225,-1.575) L11(1.575,-1.575) L12(1.925,-1.575) M2(-1.575,-1.925) M3(-1.225,-1.925) M4(-0.875,-1.925) M5(-0.525,-1.925) M6(-0.175,-1.925) M7(0.175,-1.925) M8(0.525,-1.925) M9(0.875,-1.925) M10(1.225,-1.925) M11(1.575,-1.925)
YSML65W41H20
  rect 0.508x0.991 smd: 1(-0.554,0) 2(0.554,0)
YSML79W63H20
  rect 0.94x0.838 smd: 1(-0.725,-0.575) 2(0.725,-0.575) 3(0.725,0.575) 4(-0.725,0.575)

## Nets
1V8_D: C23.2(N2) C24.1 C28.1 C32.1 C40.1 C46.1 C47.1 C49.1 C50.1 C54.1 C56.1 C58.1 C59.1 C60.1 C61.1 C76.1 C79.1 C80.1 C81.1 C82.1 C83.1 C84.1 C85.1 C87.1 C119.1 E2.2(N2) JP2.1 P9.1 R176.2(N2) U1.A6 U1.D10 U1.E1 U1.J11 U1.M4 U5.8 U6.B4 U6.D1 U6.E4 U7.B4 U7.D1 U7.E4
